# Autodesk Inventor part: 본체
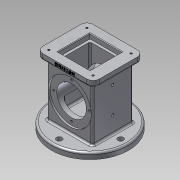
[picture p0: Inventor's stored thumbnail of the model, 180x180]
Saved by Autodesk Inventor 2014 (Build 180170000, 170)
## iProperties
Created: 2018-10
Part Number: 본체
Material: 알루미늄 6061
Document SubType Name: Modeling
Designer: Administrator
Density: 2.71 g/cm^3
Appearance: 알루미늄 - 평지
Mass: 988.221 g
Surface Area: 743.905 cm^2
Volume: 364.657 cm^3
Author: Administrator
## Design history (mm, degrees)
sketch "스케치2"
  geometry: L1 (-37, -33)-(37, -33); L2 (37, -33)-(37, 33); L3 (37, 33)-(-37, 33); L4 (-37, 33)-(-37, -33); L5 (-37, -33)-(37, 33); L6 (37, -33)-(-37, 33); 1 further point
  constraints: 12 end point, 2 midpoint, 2 parallel, 1 horizontal, 1 perpendicular
  dimensions: "d0" = 74 distance of L3.end L2.end; "d1" = 66 distance of L2.end L1.end
extrude "돌출1" new body sketch "스케치2" stored distance "d2" = 108; taper "d3" = 0 deg
sketch "스케치3"
  geometry: L1 (74, -108)-(0, -108) reference; C1 r 35 at (37, -54); 1 further point
  constraints: 1 centre point, 1 coincident
  dimensions: "d5" = 70 diameter of C1
extrude "돌출2" cut sketch "스케치3" distance "d6" = 3; taper "d7" = 0 deg
sketch "스케치4"
  geometry: L1 (0, 0)-(0, 29); C1 r 35 at (0, 0) reference; 1 further point
  constraints: 2 end point, 1 coincident, 1 vertical
  dimensions: "d9" = 29 distance of L1.start L1.end
hole "구멍1" sketch "스케치4" at (0, 29) diameter "d10" = 3.242; stored, may be unused: countersink angle "d14" = 90 deg, drill point angle "d16" = 118 deg; dims "d11" = 4, "d12" = 4, "d13" = 2, "d15" = 6
sketch "스케치6"
  geometry: L1 (37, 33)-(-37, 33) reference; L2 (37, 33)-(37, -33) reference; L3 (37, -33)-(-37, -33) reference; L4 (-37, -33)-(-37, 33) reference; L5 (-37, 33)-(37, 33) reference; L6 (37, 33)-(37, -33) reference; L7 (37, -33)-(-37, -33) reference; L8 (-37, -33)-(-37, 33) reference; L9 (-37, 33)-(37, 33) reference; L10 (46, 41)-(-46, 41); L11 (-46, 41)-(-46, -41); L12 (-46, -41)-(46, -41); L13 (46, -41)-(46, 41); L14 (46, 41)-(-46, -41); L15 (-46, 41)-(46, -41); 1 further point
  constraints: 12 end point, 2 midpoint, 2 parallel, 1 horizontal, 1 perpendicular
  dimensions: "d22" = 92 distance of L12.end L11.end; "d23" = 82 distance of L11.end L10.end
extrude "돌출3" join sketch "스케치6" distance "d24" = 10; taper "d25" = 0 deg
sketch "스케치7"
  geometry: L1 (-37, -33)-(37, -33) reference; L2 (37, -33)-(37, 33) reference; L3 (37, 33)-(-37, 33) reference; L4 (-37, 33)-(-37, -33) reference; C1 r 62.5 at (0, 0); 1 further point
  constraints: 1 centre point, 1 coincident
  dimensions: "d27" = 125 diameter of C1
extrude "돌출4" join sketch "스케치7" distance "d28" = 10; taper "d29" = 0 deg
sketch "스케치8"
  geometry: L1 (37, 33)-(-37, 33) reference; L2 (0, 0)-(0, 50); C1 r 62.5 at (0, 0) reference; 1 further point
  constraints: 2 end point, 1 coincident, 1 perpendicular
  dimensions: "d31" = 50 distance of L2.start L2.end
hole "구멍2" sketch "스케치8" at (0, 50) diameter "d32" = 9; stored, may be unused: countersink angle "d36" = 90 deg, drill point angle "d38" = 0 deg; dims "d33" = 9, "d34" = 4, "d35" = 2, "d37" = 9
sketch "스케치9"
  geometry: L1 (26, 26)-(-26, 26); L2 (-26, 26)-(-26, -26); L3 (-26, -26)-(26, -26); L4 (26, -26)-(26, 26); L5 (26, 26)-(-26, -26); L6 (-26, 26)-(26, -26); 1 further point
  constraints: 12 end point, 2 midpoint, 2 parallel, 1 horizontal, 1 perpendicular
  dimensions: "d42" = 52 distance of L3.end L2.end; "d43" = 52 distance of L2.end L1.end
extrude "돌출5" cut sketch "스케치9" distance "d44" = 8; taper "d45" = 0 deg
sketch "스케치10"
  geometry: L1 (22, 22)-(-22, 22); L2 (-22, 22)-(-22, -22); L3 (-22, -22)-(22, -22); L4 (22, -22)-(22, 22); L5 (22, 22)-(-22, -22); L6 (-22, 22)-(22, -22); 1 further point
  constraints: 12 end point, 2 midpoint, 2 parallel, 1 horizontal, 1 perpendicular
  dimensions: "d46" = 44 distance of L3.end L2.end; "d47" = 44 distance of L2.end L1.end
extrude "돌출6" cut sketch "스케치10" distance "d48" = 74; taper "d49" = 0 deg
sketch "스케치11"
  geometry: C1 r 35 at (0, 0) reference; C2 r 24 at (0, 0)
  constraints: 1 centre point, 1 coincident
  dimensions: "d50" = 48 diameter of C2
extrude "돌출7" cut sketch "스케치11" stored distance "d51" = 74; taper "d52" = 0 deg
sketch "스케치12"
  geometry: L1 (95.5, -98)-(-29.5, -98) reference; L2 (33, -98)-(33, -61); L3 (33, -61)-(33, -18); 2 further points
  constraints: 4 end point, 2 coincident, 1 collinear, 1 midpoint, 1 perpendicular
  dimensions: "d53" = 37 distance of L2.start L2.end; "d54" = 43 distance of L3.start L3.end
hole "구멍3" sketch "스케치12" at (33, -61), (33, -18) diameter "d55" = 4.134; stored, may be unused: countersink angle "d59" = 90 deg, drill point angle "d61" = 0 deg; dims "d56" = 9, "d57" = 4, "d58" = 2, "d60" = 30
fillet "모깎기1" dims "d62" = 10
sketch "스케치13"
  geometry: A1 r 10 centre (-36, 31) between (-36, 41) and (-46, 31) reference; A2 r 10 centre (-36, -31) between (-46, -31) and (-36, -41) reference; A3 r 10 centre (36, -31) between (36, -41) and (46, -31) reference; A4 r 10 centre (36, 31) between (46, 31) and (36, 41) reference; 5 further points
  constraints: 4 coincident
hole "구멍4" sketch "스케치13" at (-36, 31), (36, 31), (36, -31), (-36, -31) diameter "d63" = 3.242; stored, may be unused: countersink angle "d67" = 90 deg, drill point angle "d69" = 118 deg; dims "d64" = 4, "d65" = 4, "d66" = 2, "d68" = 6
fillet "모깎기2" dims "d70" = 3
sketch "스케치14"
  geometry: L1 (0, 0)-(72, 0) reference; L2 (-10, 0)-(-10, -10) reference; 2 further points
  constraints: 1 other
  dimensions: "d71" = 46 distance from line of point (36, -4) L2; "d72" = 4 distance from line of L1 point (36, -4)
feature "엠보싱1" sketch "스케치14" dims "d0" = 74, "d1" = 66, "d9" = 29, "d73" = 0.5, "d74" = 0
fillet "모깎기3" dims "d75" = 3
chamfer "모따기1" distance "d76" = 1; stored, may be unused: second distance "d77" = 2, angle "d78" = 45 deg
fillet "모깎기4" dims "d79" = 3
fillet "모깎기5" dims "d80" = 3
fillet "모깎기6" dims "d81" = 3
fillet "모깎기7" dims "d82" = 3
sketch "스케치15"
  geometry: C1 r 62.5 at (0, 0) reference; C2 r 28 at (0, 0)
  constraints: 1 centre point, 1 coincident
  dimensions: "d83" = 56 diameter of C2
extrude "돌출8" cut sketch "스케치15" distance "d84" = 18; taper "d85" = -10 deg
fillet "모깎기8" dims "d86" = 3
fillet "모깎기9" dims "d87" = 3
node "솔리드1"
mirror "대칭1"
pattern_circular "원형 패턴1" dims angle "d18" = 360 deg
mirror "대칭2"
pattern_circular "원형 패턴2" dims angle "d40" = 360 deg
node "절단 모서리 투영1"
node "절단 모서리 투영2"
